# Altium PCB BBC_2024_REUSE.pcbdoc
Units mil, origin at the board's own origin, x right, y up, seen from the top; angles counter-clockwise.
Board outline 1143.11 x 1156.72 mil, 2 copper layers (Top Layer, Bottom Layer); 30 components, 49 nets, 107 pads, 10 vias.
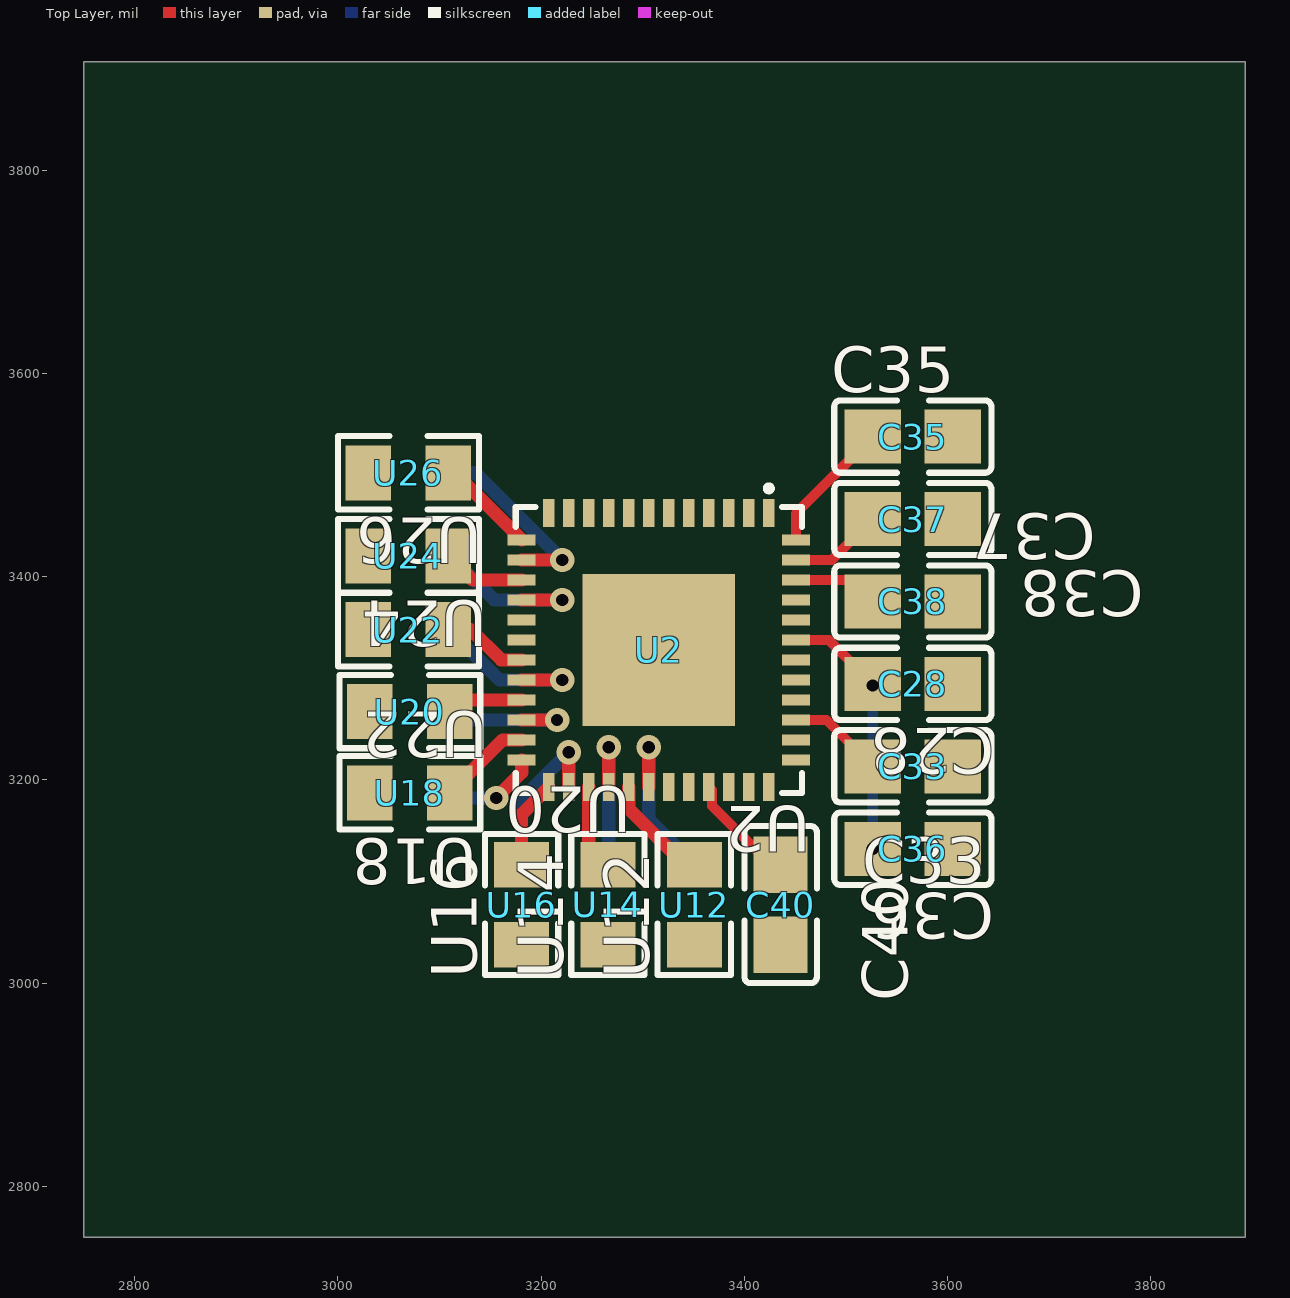
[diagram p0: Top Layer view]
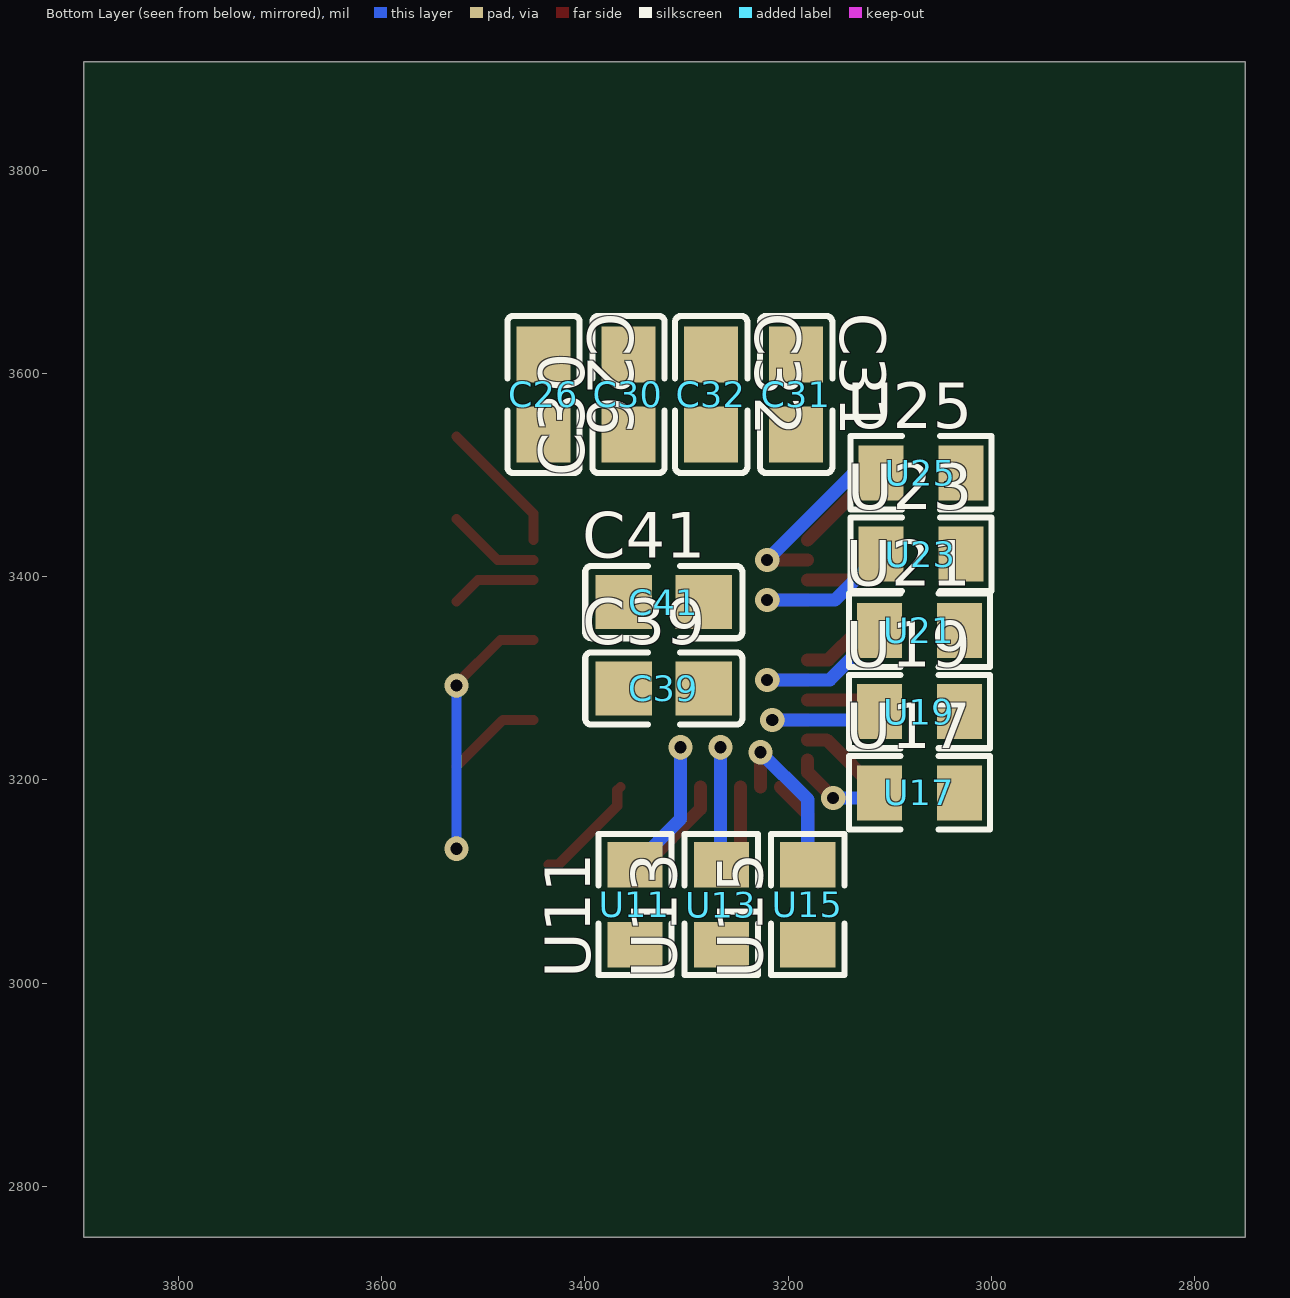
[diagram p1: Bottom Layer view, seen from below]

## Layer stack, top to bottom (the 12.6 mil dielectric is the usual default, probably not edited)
Top Layer: signal copper (thickness not stored)
Dielectric: dielectric 12.6, FR-4, Dk 4.8
Bottom Layer: signal copper (thickness not stored)

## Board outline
3893.11,2750 2750,2750 2750,3906.72 3893.11,3906.72

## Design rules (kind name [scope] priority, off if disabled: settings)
BoardOutlineClearance copperThickness1oz [All] p0: genericclearance=10 ignorepadtopadclearanceinfootprint=FALSE except(0: Arc-SplitContinuation Track-SplitContinuation SMDPad-SplitContinuation THPad-SplitContinuation Via-SplitContinuation Fill-SplitContinuation Poly-SplitContinuation Region-SplitContinuation Text-SplitContinuation; 6: Track-CutoutEdge SMDPad-CutoutEdge THPad-CutoutEdge Via-CutoutEdge Region-CutoutEdge; 11.8: Track-OutlineEdge SMDPad-OutlineEdge THPad-OutlineEdge Via-OutlineEdge Fill-OutlineEdge Region-OutlineEdge Poly-OutlineEdge Text-OutlineEdge Fill-CutoutEdge)
BoardOutlineClearance copperThickness2oz [All] p0: genericclearance=10 ignorepadtopadclearanceinfootprint=FALSE except(0: Arc-SplitContinuation Track-SplitContinuation SMDPad-SplitContinuation THPad-SplitContinuation Via-SplitContinuation Fill-SplitContinuation Poly-SplitContinuation Region-SplitContinuation Text-SplitContinuation; 6: Track-CutoutEdge SMDPad-CutoutEdge THPad-CutoutEdge Via-CutoutEdge Region-CutoutEdge; 11.8: Track-OutlineEdge SMDPad-OutlineEdge THPad-OutlineEdge Via-OutlineEdge Fill-OutlineEdge Region-OutlineEdge Poly-OutlineEdge Text-OutlineEdge Fill-CutoutEdge)
Clearance copperThickness1oz [(InNet('GND') OR InNet('BBC_DA0') OR InNet('BBC_DA2') OR InNet('BBC_DA4') OR InNet('BBC_DA6') OR InNet('BBC_DD0') OR InNet('BBC_DD2') OR InNet('BBC_DD4') OR InNet('RXIP') OR InNet('RXIN') OR InNet('BBC_CLK') OR InNet('RXQN') OR InNet('RXQP') OR InNet('DIN') OR InNet('SCLK') OR InNet('CS#') OR InNet('TXQN') OR InNet('TXQP') OR InNet('TXIN') OR InNet('TXIP') OR InNet('BBC_DD6') OR InNet('BBC_DA1') OR InNet('BBC_DA3') OR InNet('BBC_DA5') OR InNet('BBC_DA7') OR InNet('BBC_DD1') OR InNet('BBC_DD3') OR InNet('BBC_DD5') OR InNet('BBC_DD7') OR InNet('$1N1654') OR InNet('$1N1653') OR InNet('$1N1602') OR InNet('$1N1651') OR InNet('$1N1648') OR InNet('$1N1645') OR InNet('$1N1642') OR InNet('$1N1639') OR InNet('$1N1636') OR InNet('$1N1633') OR InNet('$1N1662') OR InNet('$1N1628') OR InNet('$1N1625') OR InNet('$1N1620') OR InNet('$1N1617') OR InNet('$1N1614') OR InNet('$1N1611') OR InNet('$1N1608') OR InNet('$1N1605') OR InNet('3.3'))] p1: gap=7 ignorepadtopadclearanceinfootprint=FALSE except(4: Track-Track; 6: Track-SMDPad SMDPad-SMDPad Track-THPad SMDPad-THPad THPad-THPad Track-Via SMDPad-Via THPad-Via Via-Via SMDPad-Fill THPad-Fill Via-Fill Fill-Fill Track-Region SMDPad-Region THPad-Region Via-Region Region-Region Track-Poly SMDPad-Poly THPad-Poly Via-Poly Fill-Poly Region-Poly Poly-Poly Track-Text SMDPad-Text THPad-Text Via-Text Fill-Text Region-Text Poly-Text Text-Text; 6.9: Track-Hole SMDPad-Hole THPad-Hole Via-Hole Fill-Hole Region-Hole Poly-Hole Text-Hole Sheet-Hole; 11.8: Track-Fill Fill-Region Track-Sheet SMDPad-Sheet THPad-Sheet Via-Sheet Fill-Sheet Region-Sheet Poly-Sheet Text-Sheet)
Clearance copperThickness2oz [All] p1: gap=7 ignorepadtopadclearanceinfootprint=FALSE except(6: Track-SMDPad SMDPad-SMDPad Track-THPad SMDPad-THPad THPad-THPad Track-Via SMDPad-Via THPad-Via Via-Via SMDPad-Fill THPad-Fill Via-Fill Fill-Fill Track-Region SMDPad-Region THPad-Region Via-Region Region-Region Track-Poly SMDPad-Poly THPad-Poly Via-Poly Fill-Poly Region-Poly Poly-Poly Track-Text SMDPad-Text THPad-Text Via-Text Fill-Text Region-Text Poly-Text Text-Text; 6.9: Track-Hole SMDPad-Hole THPad-Hole Via-Hole Fill-Hole Region-Hole Poly-Hole Text-Hole Sheet-Hole; 8: Track-Track; 11.8: Track-Fill Fill-Region Track-Sheet SMDPad-Sheet THPad-Sheet Via-Sheet Fill-Sheet Region-Sheet Poly-Sheet Text-Sheet)
DiffPairsRouting differentialPair [All] p1: maxuncoupledlength=10 minlimit=6 maxlimit=6 mostfreqgap=6 toplayer_minwidth=5 toplayer_prefwidth=10 toplayer_maxwidth=100 bottomlayer_minwidth=5 bottomlayer_prefwidth=10 bottomlayer_maxwidth=100
PasteMaskExpansion pasteMaskExpansion [All] p1: expansion=0
PlaneConnect innerPlane [All] p1: planeconnectstyle=Relief reliefexpansion=20 reliefentries=4 reliefconductorwidth=10 reliefairgap=10
PolygonConnect copperRegion [All] p1: connectstyle=Relief reliefentries=4 reliefconductorwidth=10 polygonreliefangle="90 Angle" airgapwidth=10
RoutingVias viaSize [All] p1: viastyle="Through Hole" holewidth=12.0078 minholewidth=11.811 maxholewidth=248.0314 width=24.0158 minwidth=19.685 maxwidth=393.7008
SolderMaskExpansion solderMaskExpansion [All] p1: useseparateexpansions=TRUE expansion=2 expansionbottom=2
Width copperThickness1oz [All] p1: maxlimit=100 minlimit=5 preferedwidth=10
Width copperThickness2oz [All] p1: maxlimit=100 minlimit=8 preferedwidth=10

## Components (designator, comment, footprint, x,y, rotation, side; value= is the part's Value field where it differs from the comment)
C26 "CAP_0805" C0805 3440.74,3579.42 r270 bottom
C28 "CAP_0805" C0805 3565.8,3294.57 r180 top
C30 "CAP_0805" C0805 3357.16,3579.42 r90 bottom
C31 "CAP_0805" C0805 3192.1,3579.42 r270 bottom
C32 "CAP_0805" C0805 3275.74,3579.42 r270 bottom
C33 "CAP_0805" C0805 3565.8,3213.44 r0 top
C35 "CAP_0805" C0805 3565.8,3537.97 r0 top
C36 "CAP_0805" C0805 3565.8,3132.31 r180 top
C37 "CAP_0805" C0805 3565.8,3456.84 r180 top
C38 "CAP_0805" C0805 3565.8,3375.7 r180 top
C39 "CAP_0805" C0805 3322.43,3290.07 r180 bottom
C40 "CAP_0805" C0805 3435.74,3077.31 r90 top
C41 "CAP_0805" C0805 3322.43,3375.07 r180 bottom
U2 "MAX5864ETM+" QFN-48_L7.0-W7.0-P0.50-BL-EP5.1 3315.8,3327.97 r180 top
U11 "3R00" R0805 3350.74,3077.31 r90 bottom
U12 "3R00" R0805 3350.74,3077.31 r90 top
U13 "3R00" R0805 3265.74,3077.31 r90 bottom
U14 "3R00" R0805 3265.74,3077.31 r90 top
U15 "3R00" R0805 3180.74,3077.31 r90 bottom
U16 "3R00" R0805 3180.74,3077.31 r90 top
U17 "3R00" R0805 3070.74,3187.31 r180 bottom
U18 "3R00" R0805 3070.74,3187.31 r180 top
U19 "3R00" R0805 3070.74,3267.31 r180 bottom
U20 "3R00" R0805 3070.74,3267.31 r180 top
U21 "3R00" R0805 3070.74,3347.31 r180 bottom
U22 "3R00" R0805 3069.34,3347.97 r180 top
U23 "3R00" R0805 3069.34,3422.31 r180 bottom
U24 "3R00" R0805 3069.34,3420.58 r180 top
U25 "3R00" R0805 3069.34,3502.31 r180 bottom
U26 "3R00" R0805 3069.34,3502.31 r180 top

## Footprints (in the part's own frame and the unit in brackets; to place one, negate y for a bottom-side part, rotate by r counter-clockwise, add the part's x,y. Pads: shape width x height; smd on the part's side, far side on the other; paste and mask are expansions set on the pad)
C0805 [mm]
  rect 1.41x1.35 smd: 1(-1,0) 2(1,0)
  silkscreen extent -1.96,-0.9 1.96,0.9
QFN-48_L7.0-W7.0-P0.50-BL-EP5.1 [mm]
  rect 0.28x0.7 smd: 1(-2.75,-3.427) 2(-2.25,-3.427) 3(-1.75,-3.427) 4(-1.25,-3.427) 5(-0.75,-3.427) 6(-0.25,-3.427) 7(0.25,-3.427) 8(0.75,-3.427) 9(1.25,-3.427) 10(1.75,-3.427) 11(2.25,-3.427) 12(2.75,-3.427) 25(2.75,3.427) 26(2.25,3.427) 27(1.75,3.427) 28(1.25,3.427) 29(0.75,3.427) 30(0.25,3.427) 31(-0.25,3.427) 32(-0.75,3.427) 33(-1.25,3.427) 34(-1.75,3.427) 35(-2.25,3.427) 36(-2.75,3.427)
  rect 0.7x0.28 smd: 13(3.427,-2.75) 14(3.427,-2.25) 15(3.427,-1.75) 16(3.427,-1.25) 17(3.427,-0.75) 18(3.427,-0.25) 19(3.427,0.25) 20(3.427,0.75) 21(3.427,1.25) 22(3.427,1.75) 23(3.427,2.25) 24(3.427,2.75) 37(-3.427,2.75) 38(-3.427,2.25) 39(-3.427,1.75) 40(-3.427,1.25) 41(-3.427,0.75) 42(-3.427,0.25) 43(-3.427,-0.25) 44(-3.427,-0.75) 45(-3.427,-1.25) 46(-3.427,-1.75) 47(-3.427,-2.25) 48(-3.427,-2.75)
  rect 3.81x3.81 smd: 49(0,0)
  silkscreen extent -3.58,-4.11 3.58,3.58
R0805 [mm]
  rect 1.133x1.377 smd: 1(-1,0) 2(1,0)
  silkscreen extent -1.76,-0.92 1.76,0.92

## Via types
v1: diameter 24.02, hole 12.01, Top Layer to Bottom Layer, 10 vias

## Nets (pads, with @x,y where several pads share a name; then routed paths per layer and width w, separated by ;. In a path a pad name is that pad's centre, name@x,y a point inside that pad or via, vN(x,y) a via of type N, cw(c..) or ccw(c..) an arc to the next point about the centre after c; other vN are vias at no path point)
3.3: C28.2 C30.1 C31.2 C32.2 C33.1 C36.2 C38.2 C39.2 C40.2 C41.2 U2.2 U2.8 U2.11 U2.18 U2.33 U2.39 U2.43 U2.46 | length 546.1
  Top Layer w10: U2.33 3368.21,3189.84 3368.21,3174.7 3426.23,3116.68 C40.2 ; U2.39 3480.8,3259.07 C33.1 ; U2.43 3483.2,3337.81 C28.2 v1(3526.43,3292.97) ; U2.46 3505.27,3396.87 C38.2
  Bottom Layer w10: v1(3526.43,3132.31) v1(3526.43,3292.97)
$1N1602: C37.2 U2.47 | length 92.4
  Top Layer w10: U2.47 3486.15,3416.55 C37.2
$1N1605: U2.30 U11.2 | length 173.5
  Top Layer w13: U2.30 v1(3305.96,3232.31)
  Bottom Layer w13: v1(3305.96,3232.31) 3305.96,3161.45 U11.2
$1N1608: U2.29 U12.2 | length 108.5
  Top Layer w13: U2.29 3286.27,3171.77 3341.37,3116.68 U12.2
$1N1611: U2.28 U13.2 | length 155.3
  Top Layer w13: U2.28 v1(3266.59,3232.31)
  Bottom Layer w13: U13.2 3266.59,3117.53 v1(3266.59,3232.31)
$1N1614: U2.27 U14.2 | length 84.2
  Top Layer w13: U2.27 3246.9,3135.51 U14.2
$1N1617: U2.26 U15.2 | length 164.2
  Top Layer w13: U2.26 v1(3227.22,3227.31)
  Bottom Layer w13: U15.2 3180.74,3180.82 v1(3227.22,3227.31)
$1N1620: U2.25 U16.2 | length 87.5
  Top Layer w13: U16.2 3180.74,3166.24 U2.25
$1N1625: U2.24 U17.1 | length 95.5
  Top Layer w13: v1(3155.74,3182.31) 3180.86,3207.43 U2.24
  Bottom Layer w13: U17.1 3115.11,3182.31 v1(3155.74,3182.31)
$1N1628: U2.23 U18.1 | length 92.3
  Top Layer w13: U18.1 3162.19,3239.39 U2.23
$1N1633: U2.21 U20.1 | length 75.5
  Top Layer w13: U20.1 3121.56,3278.76 U2.21
$1N1636: U2.20 U21.1 | length 170.7
  Top Layer w13: U2.20 v1(3220.74,3298.44)
  Bottom Layer w13: U21.1 3158.98,3298.44 v1(3220.74,3298.44)
$1N1639: U2.19 U22.1 | length 84.5
  Top Layer w13: U22.1 3130.74,3347.97 3160.58,3318.13 U2.19
$1N1642: U2.16 U23.1 | length 170.6
  Top Layer w13: U2.16 v1(3220.74,3377.18)
  Bottom Layer w13: U23.1 3153.83,3377.18 v1(3220.74,3377.18)
$1N1645: U2.15 U24.1 | length 82
  Top Layer w13: U24.1 3132.42,3396.87 U2.15
$1N1648: U2.14 U25.1 | length 187.4
  Top Layer w13: U2.14 v1(3220.74,3416.55)
  Bottom Layer w13: U25.1 3134.98,3502.31 v1(3220.74,3416.55)
$1N1651: U2.13 U26.1 | length 99.5
  Top Layer w13: U26.1 3114.8,3502.31 U2.13
$1N1653: C35.1 U2.48 | length 133.1
  Top Layer w10: U2.48 3450.74,3462.28 C35.1
$1N1654: C26.2 U2.1
$1N1662: U2.22 U19.1 | length 143.9
  Top Layer w13: U2.22 v1(3215.74,3259.07)
  Bottom Layer w13: U19.1 3118.35,3259.07 v1(3215.74,3259.07)
BBC_CLK: U2.6
BBC_DA0: U26.2
BBC_DA1: U25.2
BBC_DA2: U24.2
BBC_DA3: U23.2
BBC_DA4: U22.2
BBC_DA5: U21.2
BBC_DA6: U20.2
BBC_DA7: U19.2
BBC_DD0: U18.2
BBC_DD1: U17.2
BBC_DD2: U16.1
BBC_DD3: U15.1
BBC_DD4: U14.1
BBC_DD5: U13.1
BBC_DD6: U12.1
BBC_DD7: U11.1
CS#: U2.36
DIN: U2.34
GND: C26.1 C28.1 C30.2 C31.1 C32.1 C33.2 C35.2 C36.1 C37.1 C38.1 C39.1 C40.1 C41.1 U2.5 U2.7 U2.12 U2.17 U2.31 U2.32 U2.37 U2.42 U2.49
RXIN: U2.4
RXIP: U2.3
RXQN: U2.9
RXQP: U2.10
SCLK: U2.35
TXIN: U2.44
TXIP: U2.45
TXQN: U2.41
TXQP: U2.40
pads on no net: U2.38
